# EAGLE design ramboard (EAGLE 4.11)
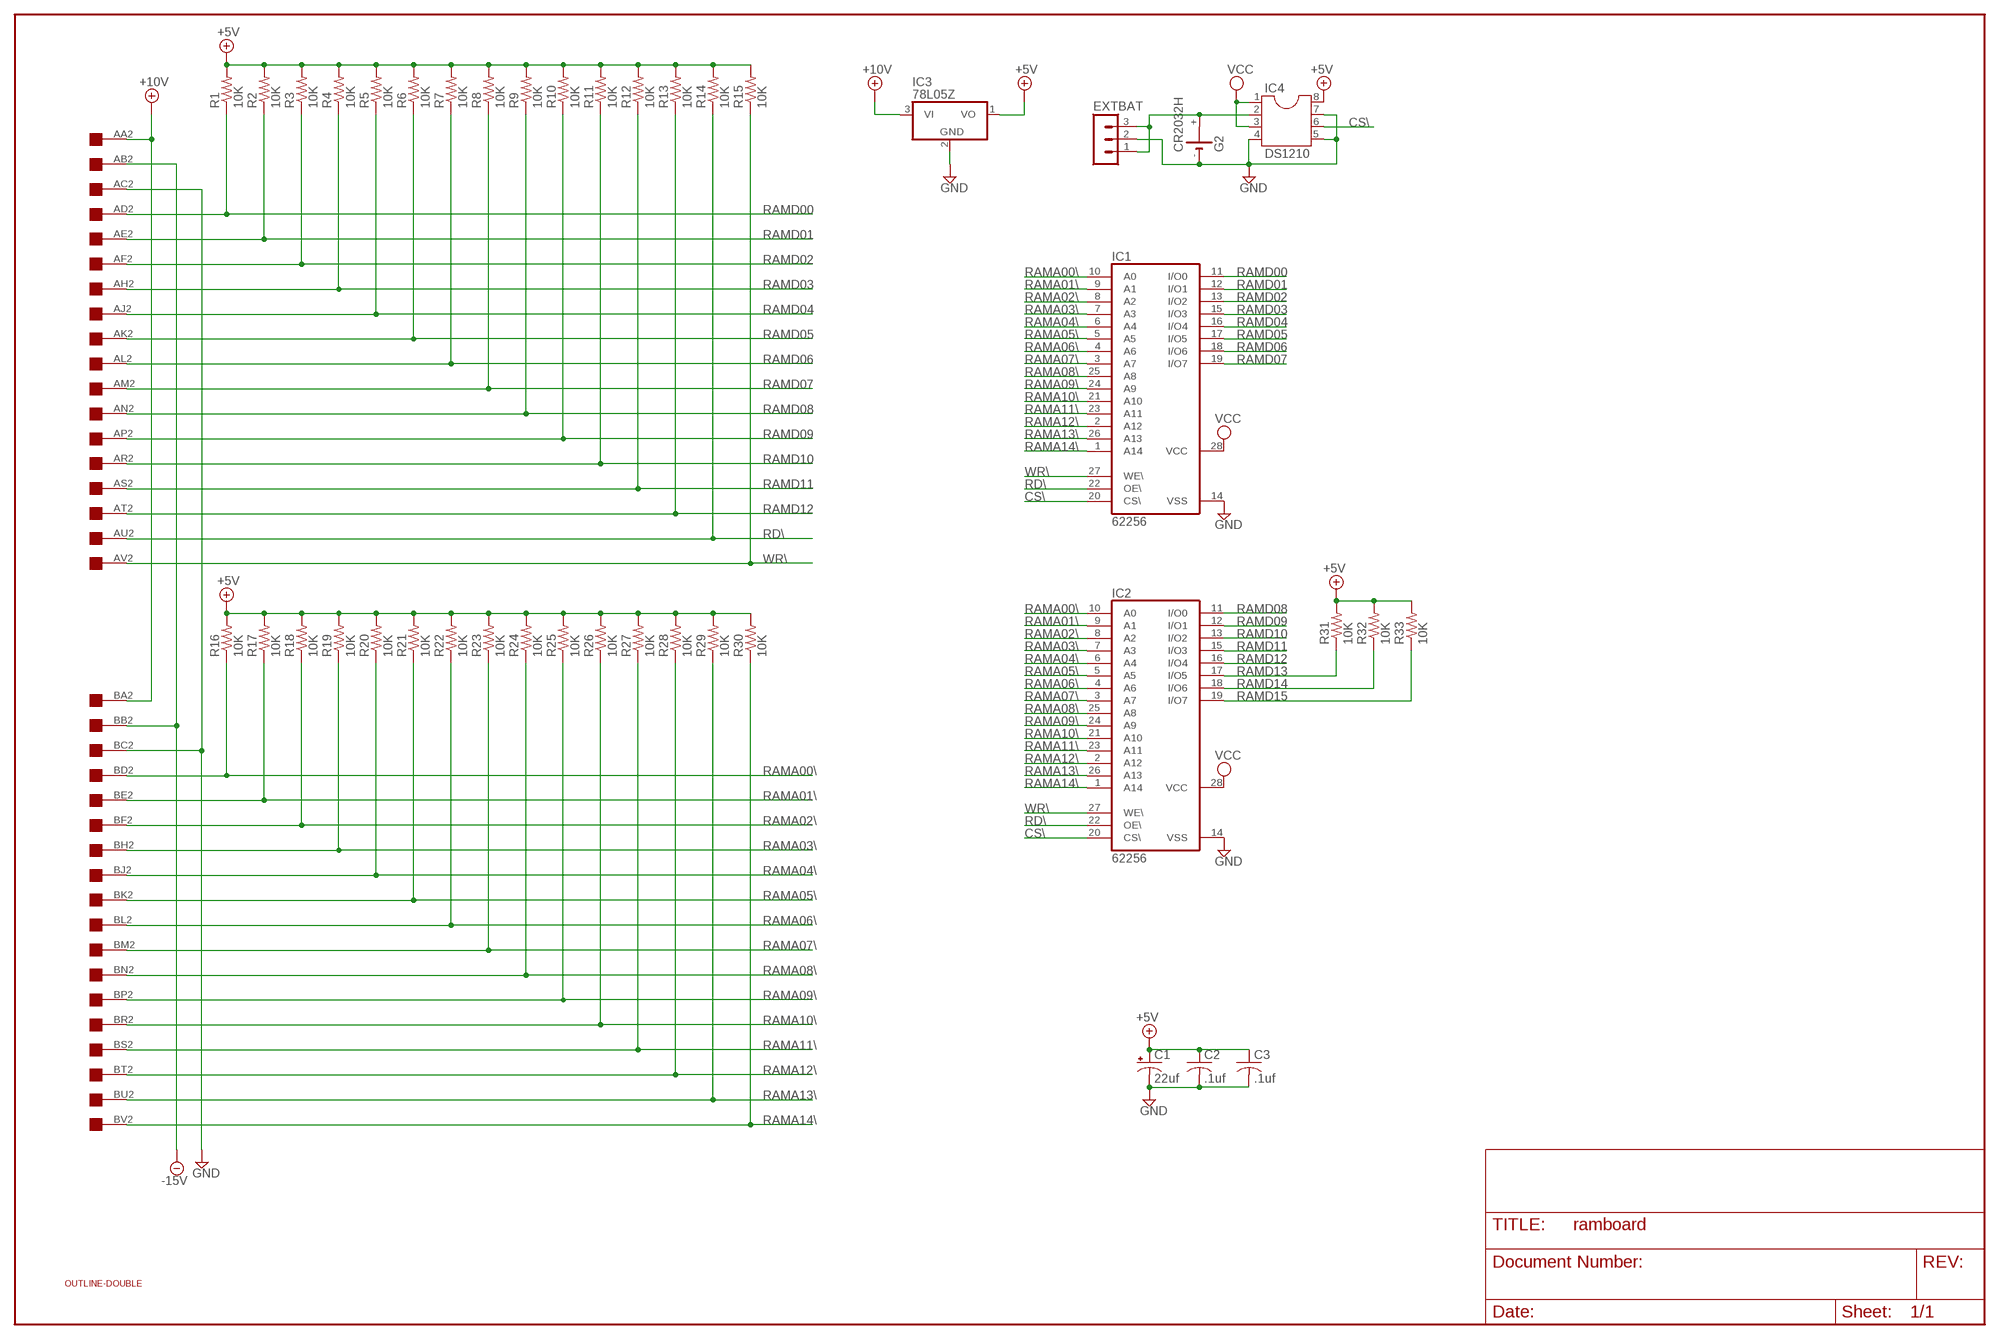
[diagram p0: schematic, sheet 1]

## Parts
C1  22uf  CPOL-USE22-6AXIAL  [E22-6]
C2  .1uf  C-US050-025X075  [C050-025X075]
C3  .1uf  C-US050-025X075  [C050-025X075]
EXTBAT  MA03-1  [MA03-1]
G2  CR2032H  [CR2032H]
IC1  62256  62256P  [DIL28-6]
IC2  62256  62256P  [DIL28-6]
IC3  78L05Z  [TO92]
IC4  DS1210  DIL8S  [SOCKED-08]
R1  10K  R-US_0207/10  [0207/10]
R2  10K  R-US_0207/10  [0207/10]
R3  10K  R-US_0207/10  [0207/10]
R4  10K  R-US_0207/10  [0207/10]
R5  10K  R-US_0207/10  [0207/10]
R6  10K  R-US_0207/10  [0207/10]
R7  10K  R-US_0207/10  [0207/10]
R8  10K  R-US_0207/10  [0207/10]
R9  10K  R-US_0207/10  [0207/10]
R10  10K  R-US_0207/10  [0207/10]
R11  10K  R-US_0207/10  [0207/10]
R12  10K  R-US_0207/10  [0207/10]
R13  10K  R-US_0207/10  [0207/10]
R14  10K  R-US_0207/10  [0207/10]
R15  10K  R-US_0207/10  [0207/10]
R16  10K  R-US_0207/10  [0207/10]
R17  10K  R-US_0207/10  [0207/10]
R18  10K  R-US_0207/10  [0207/10]
R19  10K  R-US_0207/10  [0207/10]
R20  10K  R-US_0207/10  [0207/10]
R21  10K  R-US_0207/10  [0207/10]
R22  10K  R-US_0207/10  [0207/10]
R23  10K  R-US_0207/10  [0207/10]
R24  10K  R-US_0207/10  [0207/10]
R25  10K  R-US_0207/10  [0207/10]
R26  10K  R-US_0207/10  [0207/10]
R27  10K  R-US_0207/10  [0207/10]
R28  10K  R-US_0207/10  [0207/10]
R29  10K  R-US_0207/10  [0207/10]
R30  10K  R-US_0207/10  [0207/10]
R31  10K  R-US_0207/10  [0207/10]
R32  10K  R-US_0207/10  [0207/10]
R33  10K  R-US_0207/10  [0207/10]
U$1  OUTLINE-DOUBLE  [DOUBLE]
U$2  DOUBLE  [EDGE-CON4]

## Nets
+5V: C1.+ C2.1 C3.1 IC3.1(VO) IC4.8 R1.2 R2.2 R3.2 R4.2 R5.2 R6.2 R7.2 R8.2 R9.2 R10.2 R11.2 R12.2 R13.2 R14.2 R15.2 R16.2 R17.2 R18.2 R19.2 R20.2 R21.2 R22.2 R23.2 R24.2 R25.2 R26.2 R27.2 R28.2 R29.2 R30.2 R31.2 R32.2 R33.2
+10V: IC3.3(VI) U$2.AA2 U$2.BA2
-15V: U$2.AB2 U$2.BB2
CS\: IC1.20(CS\) IC2.20(CS\) IC4.6
GND: C1.- C2.2 C3.2 EXTBAT.2 G2.- IC1.14(VSS) IC2.14(VSS) IC3.2(GND) IC4.4 IC4.5 IC4.7 U$2.AC2 U$2.BC2
N$1: EXTBAT.1 EXTBAT.3 G2.+ IC4.2
RAMA00\: IC1.10(A0) IC2.10(A0) R16.1 U$2.BD2
RAMA01\: IC1.9(A1) IC2.9(A1) R17.1 U$2.BE2
RAMA02\: IC1.8(A2) IC2.8(A2) R18.1 U$2.BF2
RAMA03\: IC1.7(A3) IC2.7(A3) R19.1 U$2.BH2
RAMA04\: IC1.6(A4) IC2.6(A4) R20.1 U$2.BJ2
RAMA05\: IC1.5(A5) IC2.5(A5) R21.1 U$2.BK2
RAMA06\: IC1.4(A6) IC2.4(A6) R22.1 U$2.BL2
RAMA07\: IC1.3(A7) IC2.3(A7) R23.1 U$2.BM2
RAMA08\: IC1.25(A8) IC2.25(A8) R24.1 U$2.BN2
RAMA09\: IC1.24(A9) IC2.24(A9) R25.1 U$2.BP2
RAMA10\: IC1.21(A10) IC2.21(A10) R26.1 U$2.BR2
RAMA11\: IC1.23(A11) IC2.23(A11) R27.1 U$2.BS2
RAMA12\: IC1.2(A12) IC2.2(A12) R28.1 U$2.BT2
RAMA13\: IC1.26(A13) IC2.26(A13) R29.1 U$2.BU2
RAMA14\: IC1.1(A14) IC2.1(A14) R30.1 U$2.BV2
RAMD00: IC1.11(I/O0) R1.1 U$2.AD2
RAMD01: IC1.12(I/O1) R2.1 U$2.AE2
RAMD02: IC1.13(I/O2) R3.1 U$2.AF2
RAMD03: IC1.15(I/O3) R4.1 U$2.AH2
RAMD04: IC1.16(I/O4) R5.1 U$2.AJ2
RAMD05: IC1.17(I/O5) R6.1 U$2.AK2
RAMD06: IC1.18(I/O6) R7.1 U$2.AL2
RAMD07: IC1.19(I/O7) R8.1 U$2.AM2
RAMD08: IC2.11(I/O0) R9.1 U$2.AN2
RAMD09: IC2.12(I/O1) R10.1 U$2.AP2
RAMD10: IC2.13(I/O2) R11.1 U$2.AR2
RAMD11: IC2.15(I/O3) R12.1 U$2.AS2
RAMD12: IC2.16(I/O4) R13.1 U$2.AT2
RAMD13: IC2.17(I/O5) R31.1
RAMD14: IC2.18(I/O6) R32.1
RAMD15: IC2.19(I/O7) R33.1
RD\: IC1.22(OE\) IC2.22(OE\) R14.1 U$2.AU2
VCC: IC1.28(VCC) IC2.28(VCC) IC4.1 IC4.3
WR\: IC1.27(WE\) IC2.27(WE\) R15.1 U$2.AV2
Unconnected: G2.+@1(+) U$2.AA1 U$2.AB1 U$2.AC1 U$2.AD1 U$2.AE1 U$2.AF1 U$2.AH1 U$2.AJ1 U$2.AK1 U$2.AL1 U$2.AM1 U$2.AN1 U$2.AP1 U$2.AR1 U$2.AS1 U$2.AT1 U$2.AU1 U$2.AV1 U$2.BA1 U$2.BB1 U$2.BC1 U$2.BD1 U$2.BE1 U$2.BF1 U$2.BH1 U$2.BJ1 U$2.BK1 U$2.BL1 U$2.BM1 U$2.BN1 U$2.BP1 U$2.BR1 U$2.BS1 U$2.BT1 U$2.BU1 U$2.BV1

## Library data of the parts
C1 = rcl:CPOL-US: POLARIZED CAPACITOR, American symbol
C2 C3 = rcl:C-US: CAPACITOR, American symbol
EXTBAT = con-lstb:MA03-1: PIN HEADER
G2 = battery:CR2032H: LI BATTERY Varta
IC1 IC2 = memory-hitachi:62256P: MEMORY
IC3 = linear:78*: Positive VOLTAGE REGULATOR
IC4 = ic-package:DIL8: Dual In Line
R1-R33 = rcl:R-US_: RESISTOR, American symbol
U$1 = dec-con:OUTLINE-*: Board outlines for DEC boards.
U$2 = dec-con:DOUBLE: Double-Height DEC board

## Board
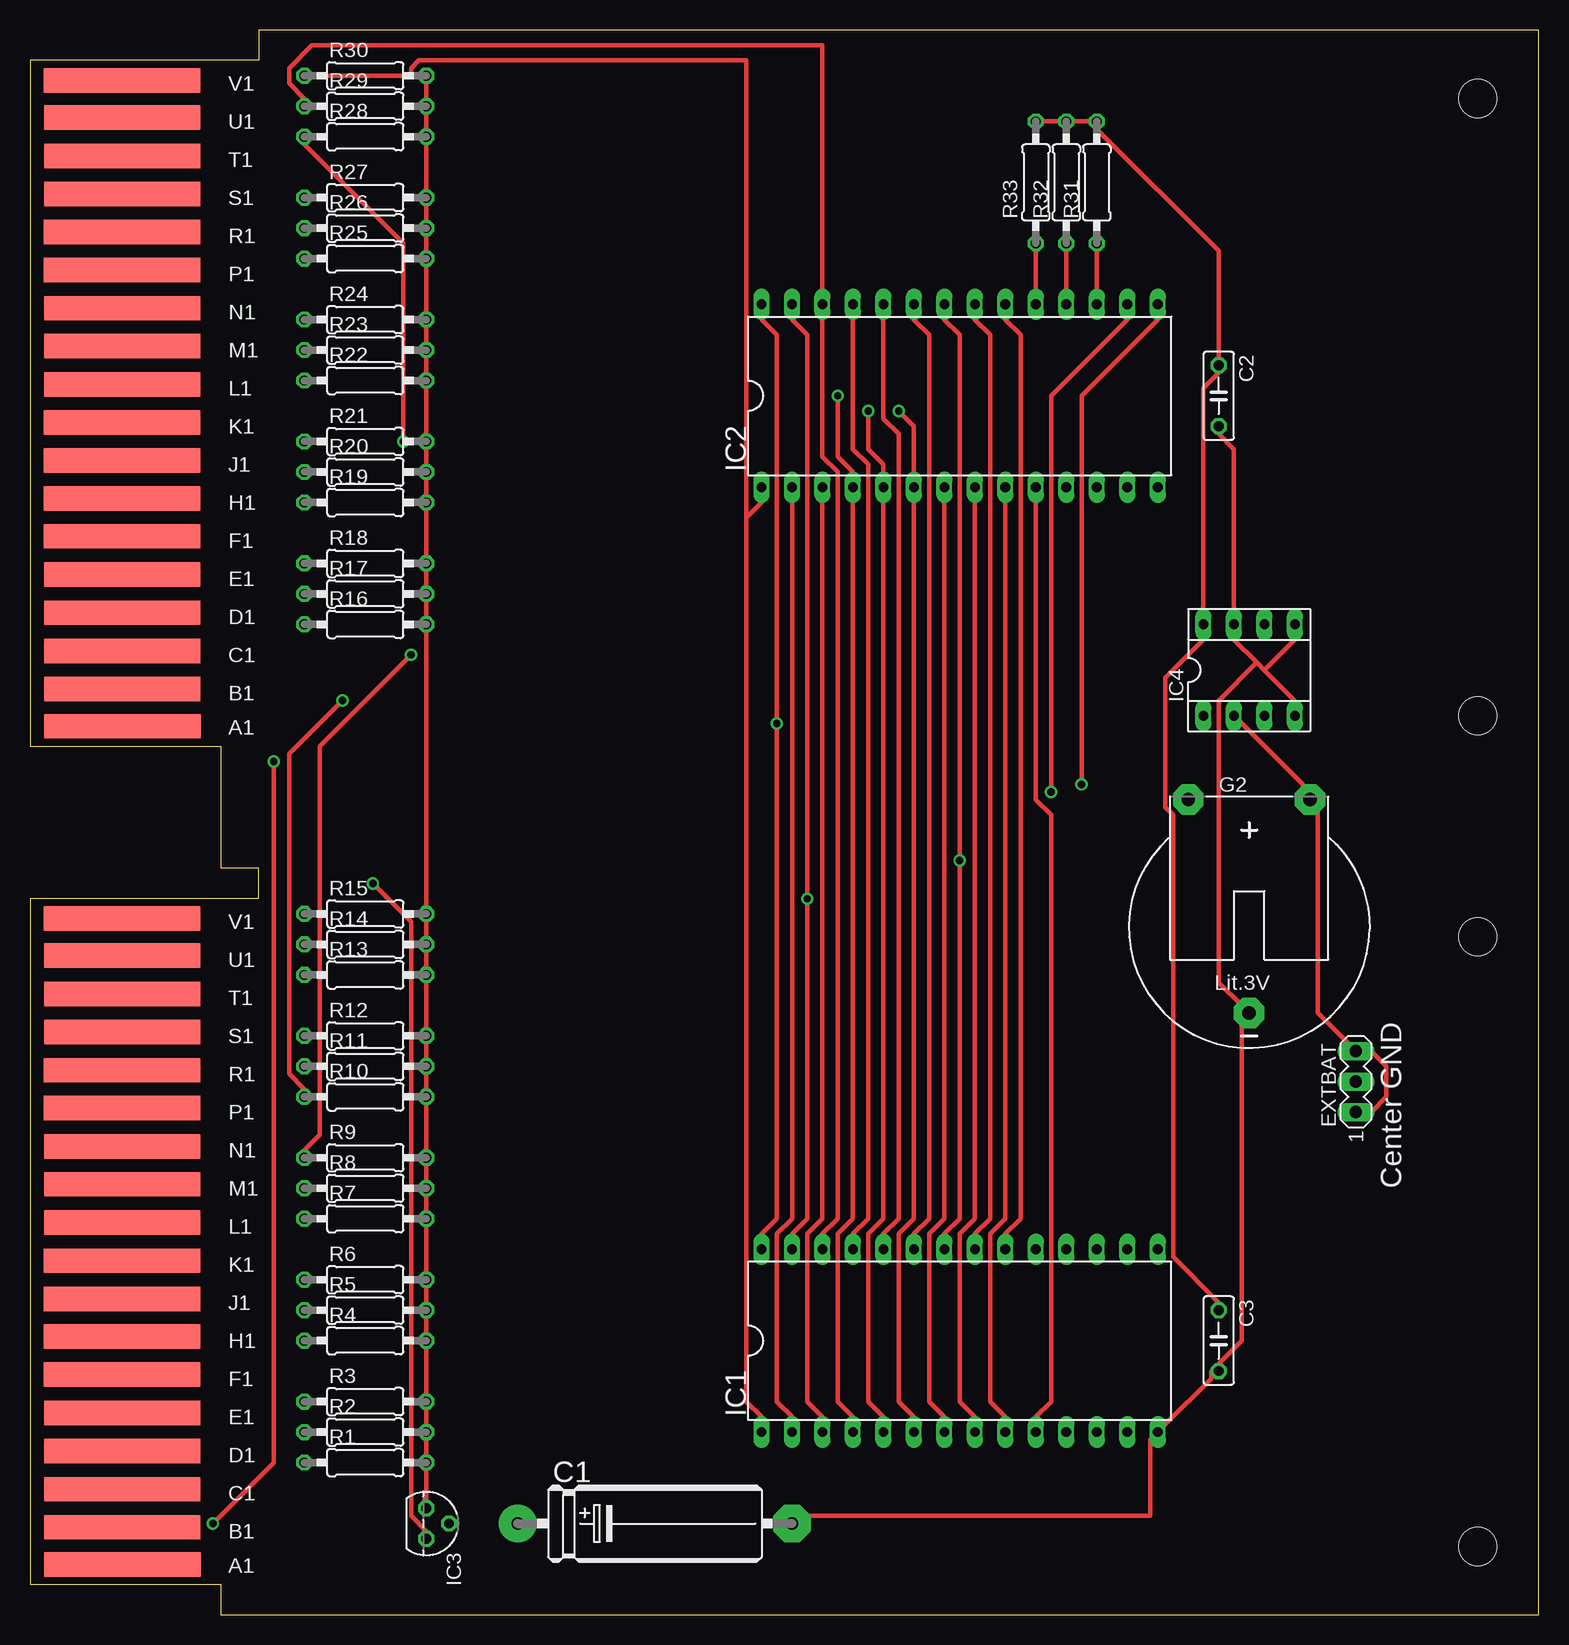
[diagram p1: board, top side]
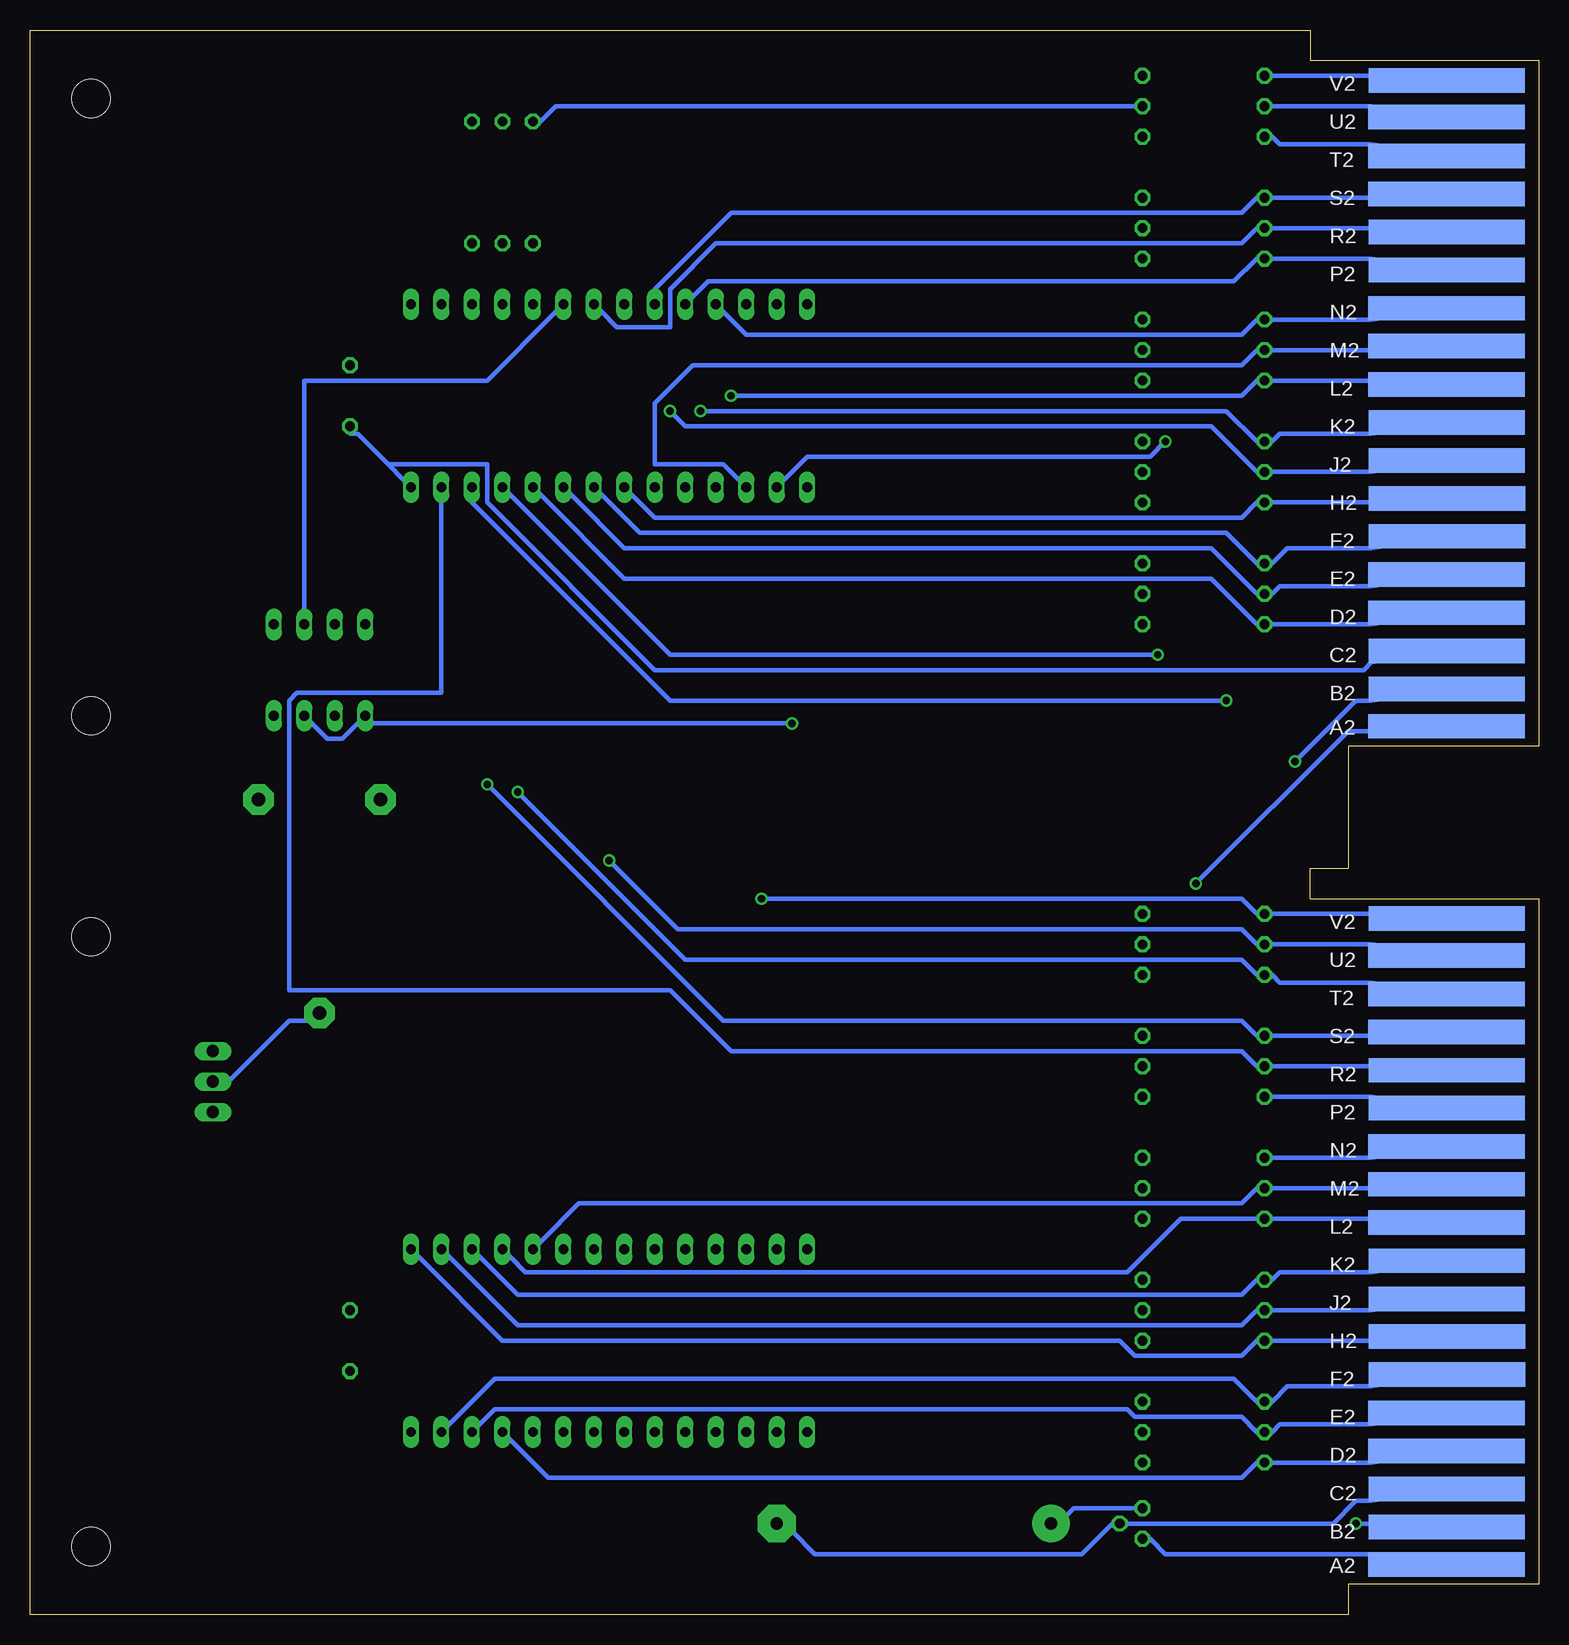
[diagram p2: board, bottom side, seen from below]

Size 125.73 x 132.08 mm. Coordinates in mm from the lower left corner, seen from the top.
Copper layers (1*16): Top 0.035mm / dielectric 1.5mm / Bottom 0.035mm
Design rules "15mils": minimum track width 15mil, minimum drill 24mil, track to track 15mil, track to pad 10mil, pad to pad 10mil, via to via 10mil, smd to smd 10mil, copper to edge 25mil, drill to drill 10mil, minimum pad ring 10mil, minimum via ring 8mil, stop-mask expansion 0mil, vias tented up to drill 0mil, thermal gap 10mil

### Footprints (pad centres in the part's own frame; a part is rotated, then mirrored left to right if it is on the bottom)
E22-6 = drill 1.016 pad 3.15 round: + -11.43,0 | drill 1.016 pad 3.15 octagon: - 11.43,0
C050-025X075 = drill 0.813 octagon: 1 -2.54,0; 2 2.54,0
MA03-1 = drill 1.016 long: 1 -2.54,0; 2 0,0; 3 2.54,0
CR2032H = drill 1.118 pad 2.54 octagon: + 5.08,10.795; +@1 -5.08,10.795; - 0,-6.985
DIL28-6 = drill 0.813 long: 1 -16.51,-7.62; 2 -13.97,-7.62; 3 -11.43,-7.62; 4 -8.89,-7.62; 5 -6.35,-7.62; 6 -3.81,-7.62; 7 -1.27,-7.62; 8 1.27,-7.62; 9 3.81,-7.62; 10 6.35,-7.62; 11 8.89,-7.62; 12 11.43,-7.62; 13 13.97,-7.62; 14 16.51,-7.62; 15 16.51,7.62; 16 13.97,7.62; 17 11.43,7.62; 18 8.89,7.62; 19 6.35,7.62; 20 3.81,7.62; 21 1.27,7.62; 22 -1.27,7.62; 23 -3.81,7.62; 24 -6.35,7.62; 25 -8.89,7.62; 26 -11.43,7.62; 27 -13.97,7.62; 28 -16.51,7.62
TO92 = drill 0.813 octagon: 1 -1.27,0; 2 0,1.905; 3 1.27,0
SOCKED-08 = drill 0.813 long: 1 -3.81,-3.81; 2 -1.27,-3.81; 3 1.27,-3.81; 4 3.81,-3.81; 5 3.81,3.81; 6 1.27,3.81; 7 -1.27,3.81; 8 -3.81,3.81
0207/10 = drill 0.813 octagon: 1 -5.08,0; 2 5.08,0
DOUBLE = hole 3.175: 120.65,56.515; 120.65,5.715; 120.65,74.93; 120.65,126.365
EDGE-CON4 = smd 13.017 x 2.032: AA1 7.709,4.207; AB1 7.684,7.312; AC1 7.684,10.474; AD1 7.684,13.665; AE1 7.693,16.84; AF1 7.668,20.041; AH1 7.668,23.19; AJ1 7.668,26.34; AK1 7.668,29.515; AL1 7.693,32.69; AM1 7.693,35.89; AN1 7.693,39.04; AP1 7.668,42.24; AR1 7.668,45.39; AS1 7.693,48.565; AT1 7.693,51.74; AU1 7.693,54.94; AV1 7.668,58.026; BA1 7.709,74.057; BB1 7.684,77.162; BC1 7.684,80.324; BD1 7.684,83.515; BE1 7.693,86.69; BF1 7.668,89.891; BH1 7.668,93.04; BJ1 7.668,96.19; BK1 7.668,99.365; BL1 7.693,102.54; BM1 7.693,105.74; BN1 7.693,108.89; BP1 7.668,112.09; BR1 7.668,115.24; BS1 7.693,118.415; BT1 7.693,121.59; BU1 7.693,124.79; BV1 7.668,127.876 | smd 13.017 x 2.032 bottom: AA2 7.69,4.207; AB2 7.668,7.328; AC2 7.668,10.49; AD2 7.693,13.665; AE2 7.693,16.84; AF2 7.642,20.041; AH2 7.642,23.19; AJ2 7.668,26.34; AK2 7.668,29.515; AL2 7.693,32.69; AM2 7.693,35.89; AN2 7.693,39.04; AP2 7.668,42.24; AR2 7.668,45.39; AS2 7.693,48.565; AT2 7.693,51.74; AU2 7.693,54.966; AV2 7.668,58.026; BA2 7.69,74.057; BB2 7.668,77.178; BC2 7.668,80.34; BD2 7.693,83.515; BE2 7.693,86.69; BF2 7.642,89.891; BH2 7.642,93.04; BJ2 7.668,96.19; BK2 7.668,99.365; BL2 7.693,102.54; BM2 7.693,105.74; BN2 7.693,108.89; BP2 7.668,112.09; BR2 7.668,115.24; BS2 7.693,118.415; BT2 7.693,121.59; BU2 7.693,124.816; BV2 7.668,127.876

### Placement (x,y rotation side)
C1  52.07,7.62 0 top
C2  99.06,101.6 270 top
C3  99.06,22.86 270 top
EXTBAT  110.49,44.45 90 top
G2  101.6,57.15 0 top
IC1  77.47,22.86 0 top
IC2  77.47,101.6 0 top
IC3  33.02,7.62 270 top
IC4  101.6,78.74 0 top
R1  27.94,12.7 0 top
R2  27.94,15.24 0 top
R3  27.94,17.78 0 top
R4  27.94,22.86 0 top
R5  27.94,25.4 0 top
R6  27.94,27.94 0 top
R7  27.94,33.02 0 top
R8  27.94,35.56 0 top
R9  27.94,38.1 0 top
R10  27.94,43.18 0 top
R11  27.94,45.72 0 top
R12  27.94,48.26 0 top
R13  27.94,53.34 0 top
R14  27.94,55.88 0 top
R15  27.94,58.42 0 top
R16  27.94,82.55 0 top
R17  27.94,85.09 0 top
R18  27.94,87.63 0 top
R19  27.94,92.71 0 top
R20  27.94,95.25 0 top
R21  27.94,97.79 0 top
R22  27.94,102.87 0 top
R23  27.94,105.41 0 top
R24  27.94,107.95 0 top
R25  27.94,113.03 0 top
R26  27.94,115.57 0 top
R27  27.94,118.11 0 top
R28  27.94,123.19 0 top
R29  27.94,125.73 0 top
R30  27.94,128.27 0 top
R31  88.9,119.38 90 top
R32  86.36,119.38 90 top
R33  83.82,119.38 90 top
U$1  0,0 0 top
U$2  0,0 0 top

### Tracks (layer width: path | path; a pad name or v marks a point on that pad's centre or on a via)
+5V
  Top 0.381: R33.2 84.46,124.46 85.73,124.46 R32.2 87,124.46 88.27,124.46 R31.2 88.9,123.83 99.06,113.67 99.06,104.78 C2.1 99.06,103.5 97.79,102.23 97.79,83.82 IC4.8 97.79,81.28 94.62,78.11 94.62,67.31 95.25,66.67 95.25,29.84 99.06,26.04 C3.1 | R30.2 33.02,127.64 33.02,126.36 R29.2 33.02,125.09 33.02,123.83 R28.2 33.02,122.56 33.02,118.75 R27.2 33.02,117.47 33.02,116.2 R26.2 33.02,114.94 33.02,113.67 R25.2 33.02,112.39 33.02,108.58 R24.2 33.02,107.31 33.02,106.05 R23.2 33.02,104.78 33.02,103.5 R22.2 33.02,102.23 33.02,98.42 R21.2 33.02,97.16 33.02,95.89 R20.2 33.02,94.61 33.02,93.34 R19.2 33.02,92.08 33.02,88.27 R18.2 33.02,87 33.02,85.72 R17.2 33.02,84.45 33.02,83.19 R16.2 33.02,81.92 33.02,59.05 R15.2 33.02,57.78 33.02,56.52 R14.2 33.02,55.24 33.02,53.98 R13.2 33.02,52.7 33.02,48.9 R12.2 33.02,47.62 33.02,46.35 R11.2 33.02,45.09 33.02,43.81 R10.2 33.02,42.55 33.02,38.73 R9.2 33.02,37.47 33.02,36.2 R8.2 33.02,34.92 33.02,33.66 R7.2 33.02,32.38 33.02,28.57 R6.2 33.02,27.3 33.02,26.04 R5.2 33.02,24.77 33.02,23.5 R4.2 33.02,22.23 33.02,18.41 R3.2 33.02,17.14 33.02,15.88 R2.2 33.02,14.61 33.02,13.34 R1.2 33.02,12.06 33.02,9.53 IC3.1
  Bottom 0.381: C1.+ 39.37,8.26 38.74,8.89 33.66,8.89 IC3.1 | R33.2 83.19,124.46 81.92,125.73 33.66,125.73 R29.2
+10V  (via drill 0.61)
  Top 0.381: v28.58,60.96 31.75,57.78 31.75,8.26 33.02,6.99 IC3.3
  Bottom 0.381: IC3.3 32.39,6.35 31.12,5.08 13.97,5.08 U$2.AA2 | v28.58,60.96 15.88,73.66 13.97,73.66 U$2.BA2
-15V  (via drill 0.61)
  Top 0.381: v15.24,7.62 20.32,12.7 v20.32,71.12
  Bottom 0.381: v15.24,7.62 13.97,7.62 U$2.AB2 | v20.32,71.12 15.24,76.2 13.97,76.2 U$2.BB2
CS\
  Top 0.381: IC1.20 81.28,31.75 82.55,33.02 82.55,106.68 81.28,107.95 IC2.20
  Bottom 0.381: IC4.6 102.87,83.82 102.87,102.87 87.63,102.87 81.92,108.58 IC2.20
GND
  Top 0.381: 102.87,78.74 105.41,76.2 IC4.4 | 102.24,79.38 102.87,78.74 | 102.24,79.38 100.33,81.28 IC4.7 100.33,83.82 100.33,97.16 99.06,98.42 C2.2 | 102.87,78.74 105.41,81.28 IC4.5 | C1.- 64.77,8.26 93.35,8.26 93.35,14.61 IC1.14 94.62,15.88 98.43,19.68 98.43,20.32 C3.2 99.06,20.95 100.97,22.86 100.97,49.53 G2.- 100.97,50.8 99.06,52.7 99.06,76.2 102.24,79.38
  Bottom 0.381: 95.89,95.89 98.43,98.42 99.06,98.42 C2.2 | 95.89,95.89 94.62,94.61 IC2.14 | 95.89,95.89 87.63,95.89 87.63,92.71 73.66,78.74 14.61,78.74 13.97,79.38 U$2.BC2 | U$2.AC2 13.97,9.53 15.24,9.53 17.15,7.62 34.29,7.62 IC3.2 35.56,7.62 38.1,5.08 60.33,5.08 62.23,6.99 C1.- | EXTBAT.2 109.22,44.45 104.14,49.53 102.24,49.53 G2.-
N$1
  Top 0.381: EXTBAT.1 111.76,41.91 113.03,43.18 113.03,45.72 111.76,46.99 EXTBAT.3 109.86,47.62 107.32,50.16 107.32,67.31 G2.+ 106.05,68.58 106.05,69.22 100.97,74.3 IC4.2
RAMA00\
  Top 0.381: IC1.10 83.82,16.51 85.09,17.78 85.09,66.67 83.82,67.94 83.82,92.71 IC2.10
  Bottom 0.381: U$2.BD2 13.97,82.55 22.23,82.55 R16.1 23.5,82.55 27.31,86.36 76.2,86.36 83.19,93.34 IC2.10
RAMA01\
  Top 0.381: IC1.9 81.28,16.51 80.01,17.78 80.01,31.75 81.28,33.02 81.28,92.71 IC2.9
  Bottom 0.381: U$2.BE2 13.97,85.72 21.59,85.72 22.23,85.09 R17.1 23.5,85.09 27.31,88.9 76.2,88.9 80.65,93.34 IC2.9
RAMA02\
  Top 0.381: IC1.8 78.74,16.51 77.47,17.78 77.47,31.75 78.74,33.02 78.74,92.71 IC2.8
  Bottom 0.381: U$2.BF2 13.97,88.9 20.96,88.9 22.23,87.63 R18.1 23.5,87.63 26.04,90.17 74.93,90.17 78.11,93.34 IC2.8
RAMA03\
  Top 0.381: IC1.7 76.2,16.51 74.93,17.78 74.93,31.75 76.2,33.02 76.2,92.71 IC2.7
  Bottom 0.381: U$2.BH2 13.97,92.71 22.23,92.71 R19.1 23.5,92.71 24.77,91.44 73.66,91.44 75.57,93.34 IC2.7
RAMA04\  (via drill 0.61)
  Top 0.381: IC1.6 73.66,16.51 72.39,17.78 72.39,31.75 73.66,33.02 73.66,92.71 IC2.6 73.66,95.25 73.66,99.06 v72.39,100.33
  Bottom 0.381: U$2.BJ2 13.97,95.25 22.23,95.25 R20.1 23.5,95.25 27.31,99.06 71.12,99.06 v72.39,100.33
RAMA05\  (via drill 0.61)
  Top 0.381: IC1.5 71.12,16.51 69.85,17.78 69.85,31.75 71.12,33.02 71.12,92.71 IC2.5 71.12,95.25 71.12,95.89 69.85,97.16 v69.85,100.33
  Bottom 0.381: U$2.BK2 13.97,98.42 21.59,98.42 22.23,97.79 R21.1 23.5,97.79 26.04,100.33 v69.85,100.33
RAMA06\  (via drill 0.61)
  Top 0.381: IC1.4 68.58,16.51 67.31,17.78 67.31,31.75 68.58,33.02 68.58,92.71 IC2.4 68.58,95.25 67.31,96.52 v67.31,101.6
  Bottom 0.381: U$2.BL2 13.97,102.87 22.23,102.87 R22.1 23.5,102.87 24.77,101.6 v67.31,101.6
RAMA07\
  Top 0.381: IC1.3 66.04,16.51 64.77,17.78 64.77,31.75 66.04,33.02 66.04,92.71 IC2.3
  Bottom 0.381: U$2.BM2 13.97,105.41 22.23,105.41 R23.1 23.5,105.41 24.77,104.14 70.49,104.14 73.66,100.97 73.66,95.89 67.95,95.89 66.68,94.61 IC2.3
RAMA08\
  Top 0.381: IC1.25 68.58,31.75 69.85,33.02 69.85,95.89 68.58,97.16 68.58,107.95 IC2.25
  Bottom 0.381: U$2.BN2 13.97,107.95 22.23,107.95 R24.1 23.5,107.95 24.77,106.68 66.04,106.68 67.95,108.58 IC2.25
RAMA09\
  Top 0.381: IC1.24 71.12,31.75 72.39,33.02 72.39,98.42 71.12,99.69 71.12,107.95 IC2.24
  Bottom 0.381: U$2.BP2 13.97,113.03 22.23,113.03 R25.1 23.5,113.03 25.4,111.12 69.22,111.12 70.49,109.86 IC2.24
RAMA10\
  Top 0.381: IC1.21 78.74,31.75 80.01,33.02 80.01,106.68 78.74,107.95 IC2.21
  Bottom 0.381: U$2.BR2 13.97,115.57 22.23,115.57 R26.1 23.5,115.57 24.77,114.3 68.58,114.3 72.39,110.49 72.39,107.31 76.84,107.31 78.11,108.58 IC2.21
RAMA11\
  Top 0.381: IC1.23 73.66,31.75 74.93,33.02 74.93,106.68 73.66,107.95 IC2.23
  Bottom 0.381: U$2.BS2 13.97,118.11 22.23,118.11 R27.1 23.5,118.11 24.77,116.84 67.31,116.84 73.66,110.49 IC2.23
RAMA12\  (via drill 0.61)
  Top 0.381: IC1.2 63.5,16.51 62.23,17.78 62.23,31.75 63.5,33.02 63.5,92.71 IC2.2 | v31.12,97.79 31.12,114.3 22.86,122.56 R28.1
  Bottom 0.381: R28.1 22.23,123.19 21.59,122.56 13.97,122.56 U$2.BT2 | v31.12,97.79 32.39,96.52 60.96,96.52 62.87,94.61 IC2.2
RAMA13\
  Top 0.381: IC1.26 66.04,31.75 67.31,33.02 67.31,95.25 66.04,96.52 66.04,107.95 IC2.26 66.04,110.49 66.04,130.81 23.5,130.81 21.59,128.91 21.59,127.64 22.86,126.36 R29.1
  Bottom 0.381: R29.1 22.23,125.73 13.97,125.73 U$2.BU2
RAMA14\
  Top 0.381: 59.69,91.44 59.69,17.78 60.96,16.51 IC1.1 | 59.69,91.44 60.96,92.71 IC2.1 | 59.69,91.44 59.69,129.54 32.39,129.54 31.75,128.91 31.75,128.27 23.5,128.27 R30.1
  Bottom 0.381: R30.1 22.23,128.27 13.97,128.27 U$2.BV2
RAMD00
  Bottom 0.381: U$2.AD2 13.97,12.7 22.23,12.7 R1.1 23.5,12.7 24.77,11.43 82.55,11.43 85.73,14.61 IC1.11
RAMD01
  Bottom 0.381: U$2.AE2 13.97,15.88 21.59,15.88 22.23,15.24 R2.1 23.5,15.24 24.77,16.51 33.66,16.51 34.29,17.14 87,17.14 88.27,15.88 IC1.12
RAMD02
  Bottom 0.381: U$2.AF2 13.97,19.05 20.96,19.05 22.23,17.78 R3.1 23.5,17.78 25.4,19.68 87,19.68 90.81,15.88 IC1.13
RAMD03
  Bottom 0.381: U$2.AH2 13.97,22.86 22.23,22.86 R4.1 23.5,22.86 24.77,21.59 33.66,21.59 34.93,22.86 86.36,22.86 93.35,29.84 IC1.15
RAMD04
  Bottom 0.381: U$2.AJ2 13.97,25.4 22.23,25.4 R5.1 23.5,25.4 24.77,24.13 85.09,24.13 90.81,29.84 IC1.16
RAMD05
  Bottom 0.381: U$2.AK2 13.97,28.57 21.59,28.57 22.23,27.94 R6.1 23.5,27.94 24.77,26.67 85.09,26.67 88.27,29.84 IC1.17
RAMD06
  Bottom 0.381: U$2.AL2 13.97,33.02 22.23,33.02 R7.1 23.5,33.02 29.85,33.02 34.29,28.57 84.46,28.57 85.73,29.84 IC1.18
RAMD07
  Bottom 0.381: U$2.AM2 13.97,35.56 22.23,35.56 R8.1 23.5,35.56 24.77,34.29 80.01,34.29 83.19,31.11 IC1.19
RAMD08  (via drill 0.61)
  Top 0.381: v31.75,80.01 24.13,72.39 24.13,40.01 22.86,38.73 R9.1
  Bottom 0.381: R9.1 22.23,38.1 13.97,38.1 U$2.AN2 | v31.75,80.01 72.39,80.01 85.73,93.34 IC2.11
RAMD09  (via drill 0.61)
  Top 0.381: v26.04,76.2 21.59,71.75 21.59,45.09 22.86,43.81 R10.1
  Bottom 0.381: R10.1 22.23,43.18 13.97,43.18 U$2.AP2 | v26.04,76.2 72.39,76.2 88.9,92.71 IC2.12
RAMD10
  Bottom 0.381: U$2.AR2 13.97,45.72 22.23,45.72 R11.1 23.5,45.72 24.77,46.99 67.31,46.99 72.39,52.07 104.14,52.07 104.14,76.2 103.51,76.83 91.44,76.83 91.44,92.71 IC2.13
RAMD11  (via drill 0.61)
  Top 0.381: v87.63,69.22 87.63,101.6 93.98,107.95 IC2.15
  Bottom 0.381: U$2.AS2 13.97,48.26 22.23,48.26 R12.1 23.5,48.26 24.77,49.53 67.95,49.53 v87.63,69.22
RAMD12  (via drill 0.61)
  Top 0.381: v85.09,68.58 85.09,101.6 91.44,107.95 IC2.16
  Bottom 0.381: U$2.AT2 13.97,52.7 21.59,52.7 22.23,53.34 R13.1 23.5,53.34 24.77,54.61 71.12,54.61 v85.09,68.58
RAMD13
  Top 0.381: IC2.17 88.9,110.49 88.9,113.67 R31.1
RAMD14
  Top 0.381: IC2.18 86.36,110.49 86.36,113.67 R32.1
RAMD15
  Top 0.381: IC2.19 83.82,110.49 83.82,113.67 R33.1
RD\  (via drill 0.61)
  Top 0.381: IC1.22 76.2,31.75 77.47,33.02 v77.47,62.87 77.47,106.68 76.2,107.95 IC2.22
  Bottom 0.381: U$2.AU2 13.97,55.88 22.23,55.88 R14.1 23.5,55.88 24.77,57.15 71.76,57.15 v77.47,62.87
VCC  (via drill 0.61)
  Top 0.381: IC1.28 60.96,31.75 62.23,33.02 v62.23,74.3 62.23,106.68 60.96,107.95 IC2.28
  Bottom 0.381: IC4.3 102.24,74.3 100.97,73.03 99.7,73.03 98.43,74.3 IC4.1 97.16,74.3 v62.23,74.3
WR\  (via drill 0.61)
  Top 0.381: IC1.27 63.5,31.75 64.77,33.02 v64.77,59.69 64.77,106.68 63.5,107.95 IC2.27
  Bottom 0.381: U$2.AV2 13.97,58.42 22.23,58.42 R15.1 23.5,58.42 24.77,59.69 v64.77,59.69

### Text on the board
tPlace: Center GND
